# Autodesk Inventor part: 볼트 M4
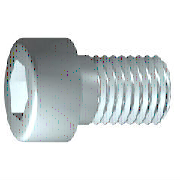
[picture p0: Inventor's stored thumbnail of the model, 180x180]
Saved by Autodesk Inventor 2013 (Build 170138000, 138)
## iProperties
IsCustomPart: 0
Created: 2012-02
Part Number: 볼트 M4
Material: 강철, 연강
Description: 6각 소켓 머리 캡 나사
Document SubType Name: Modeling
Standard: ISO 4762
Designer: mduedu
Standard Revision: Fourth edition 2004-03-01
Standards Organization: ISO
Language: ko-KR
Size Designation: M4 x 12
Categories: <MemberInstance><Categories><Category DisplayName="조임쇠" InternalName="e4da775c-781d-43d5-af7c-5136215cf5a6" Mnemonic="FSTN"><Category DisplayName="볼트" InternalN
Density: 7.75 g/cm^3
Author: mduedu
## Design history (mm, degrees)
sketch "스케치1"
  geometry: L1 (-1, 0)-(12, 0); L2 (12, 0)-(12, 2); L3 (12, 2)-(1.75, 2); L4 (1.75, 2)-(1.32, 2); L5 (1.32, 2)-(0, 2); L6 (0, 2)-(0, 3.5); L7 (0, 3.5)-(-4, 3.5); L8 (-4, 3.5)-(-4, 1.732); L9 (-4, 1.732)-(-2, 1.732); L10 (-2, 1.732)-(-1, 0); L11 (-7.2, 0)-(15.2, 0) reference; L12 (0, -0.7)-(0, 4.2) reference; L13 (1.75, 2)-(0, 2)
  constraints: 22 end point, 6 parallel, 2 collinear, 2 perpendicular, 1 horizontal, 1 point on line
  dimensions: "d1" = 10.25 distance from line of L3.end L2 (= GEL); "d2" = 0.42952 distance of L4.end L3.end (computed from GAL); "d3" = 4 distance between parallel lines of L8 L6 (= KOH); "d4" = 2 distance of L8.end L9.end (= INTI); "d5" = 60 deg angle of L10 L1; "d6" = 4 diameter of L3 L1 (= GD); "d7" = 4 diameter of L5 L1 (= BDM); "d8" = 3.4641 diameter of L9 L1 (= 1.1547 x SW); "d9" = 7 diameter of L7 L1 (= KOD); "d26" = 12 distance between parallel lines of L12 L2 (= NLG)
revolve "본체" sketch "스케치1" stored, may be unused: angle "d10" = 90 deg
sketch "스케치2"
  geometry: L1 (0, -4.9)-(0, 4.9) reference; L2 (-4.9, 0)-(4.9, 0) reference; L3 (1.732, 0)-(0.866, -1.5); L4 (0.866, -1.5)-(-0.866, -1.5); L5 (-0.866, -1.5)-(-1.732, 0); L6 (-1.732, 0)-(-0.866, 1.5); L7 (-0.866, 1.5)-(0.866, 1.5); L8 (0.866, 1.5)-(1.732, 0); 2 further points
  constraints: 12 end point, 1 coincident, 1 horizontal alignment, 1 point on line, 12 other
extrude "슬롯" join sketch "스케치2" stored distance "d11" = 10; taper "d12" = 0 deg
workplane "Work Plane1"
fillet "Fillet2" dims "d30" = 0.1 (= R)
body "Solid1"
fillet "모깎기1" dims "d17" = 0.4 (= RR)
feature "스레드" dims "d13" = 10.25 (= GEL), "d14" = 0
chamfer "모따기1" distance "d15" = 0.42941 (= -0.5 x SPD + 0.5 x GD); stored, may be unused: second distance "d16" = 0.42941 (= GUL), angle "d27" = 45 deg
other parameters: "GD" = 4 [user parameter; used in 2 equation terms], "NLG" = 12 [user parameter; used in 1 equation term], "GEL" = 10.25 [user parameter; used in 2 equation terms], "KOD" = 7 [user parameter; used in 1 equation term], "KOH" = 4 [user parameter; used in 1 equation term], "INTI" = 2 [user parameter; used in 1 equation term], "GAL" = 0.42941 (= 0.61345 x PTC) [user parameter; used in 1 equation term], "GUL" = 0.42941 (= 0.61345 x PTC) [user parameter; used in 1 equation term], "BDM" = 4 (= NND) [user parameter; used in 1 equation term], "SW" = 3 [user parameter; used in 2 equation terms], "RR" = 0.4 [user parameter; used in 1 equation term], "SPD" = 3.14117 (= NND - 1.2269 x PTC) [user parameter; used in 1 equation term], "d19" = 0, "d28" = 0, "d29" = 0, "R" = 0.1 [user parameter; used in 1 equation term], "TOA" = 30 deg [user parameter], "GD1" = 3.14117 (= THREADDIA - 1.2269 x PTC) [user parameter], "THREADDIA" = 4 [user parameter; used in 1 equation term], "FAWI" = 45 deg [user parameter], "TPU" = 14.28571 (computed from PTC) [user parameter], "PTC" = 0.7 [user parameter; used in 5 equation terms], "NND" = 4 [user parameter; used in 2 equation terms], "E0" = 3.465 (= 1.155 x SW) [user parameter]
